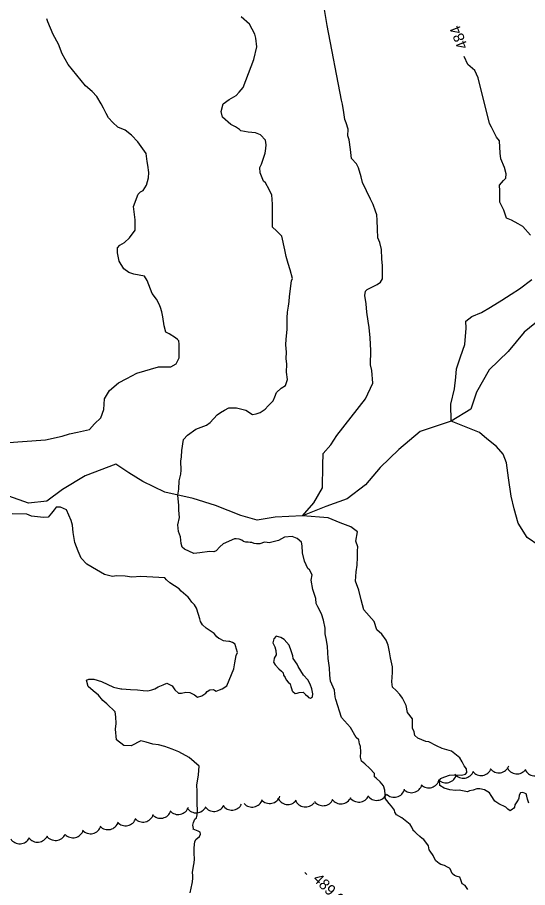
# Model space of a CAD drawing. Extents: x 642515 to 647219, y 6080136 to 6084356.
# Drawn here: x 644245.5 to 644387.6, y 6080895.6 to 6081138.3 of the extents above; entities that cross this region are included whole.
import ezdxf

# ---------------------------------------------------------------- set-up
doc = ezdxf.new("R2010")
doc.units = 0
for name, color, linetype in [('Level 1', 7, 'Continuous'), ('Level 2', 7, 'Continuous'), ('Level 3', 7, 'Continuous'), ('Level 4', 7, 'Continuous'), ('Level 44', 7, 'Continuous')]:
    doc.layers.add(name, color=color, linetype=linetype)

msp = doc.modelspace()

# ---------------------------------------------------------------- linework, layer by layer
at = {"layer": 'Level 1'}
for points in [[(644241.77, 6081019.67), (644253.35, 6081020.45), (644257.97, 6081021.56), (644260.03, 6081022.19), (644262.26, 6081022.66), (644265.61, 6081023.37), (644266.96, 6081024.91), (644268.78, 6081026.65), (644269.6, 6081028.97), (644269.73, 6081031.88), (644271.19, 6081034.24), (644273.64, 6081036.35), (644275.97, 6081037.63), (644278.79, 6081039.12), (644284.81, 6081040.81), (644288.2, 6081040.88), (644289.69, 6081041.7), (644290.54, 6081043.37), (644290.54, 6081047.17), (644290.47, 6081048.14), (644290.13, 6081048.44), (644289.53, 6081048.96), (644287.76, 6081050.06), (644286.84, 6081050.56), (644286.4, 6081052.31), (644285.99, 6081054.79), (644285.73, 6081056.23), (644285.41, 6081057.42), (644285.03, 6081058.36), (644284.21, 6081059.68), (644283.05, 6081061.3), (644281.68, 6081064.92), (644280.95, 6081066.17), (644277.93, 6081066.69), (644276.52, 6081067.17), (644275.16, 6081068.21), (644273.81, 6081070.3), (644273.41, 6081072.62), (644273.4, 6081073.99), (644274.08, 6081074.76), (644275.32, 6081075.49), (644276.77, 6081076.8), (644278.33, 6081078.92), (644278.3, 6081081.83), (644277.81, 6081085.6), (644279.12, 6081089), (644279.8, 6081089.61), (644280.5, 6081090.06), (644281.46, 6081091.5), (644282.05, 6081093.56), (644282.11, 6081095.02), (644281.81, 6081097.1), (644281.66, 6081098.14), (644281.35, 6081100.38), (644279.04, 6081103.62), (644277.3, 6081105.44), (644275.51, 6081106.86), (644273.51, 6081107.69), (644272.06, 6081108.97), (644270.92, 6081110.27), (644270.19, 6081111.51), (644269.53, 6081113), (644268.88, 6081114.17), (644267.62, 6081116.19), (644266.31, 6081117.64), (644264.51, 6081119.22), (644259.67, 6081125.12), (644257.94, 6081128.15), (644256.95, 6081130.83), (644255.48, 6081133.48), (644253.95, 6081137.1), (644253.73, 6081137.86)], [(644256.3, 6081001.69), (644255.7, 6081001), (644255.03, 6081000.07), (644254.05, 6080998.95), (644252.77, 6080998.87), (644249.43, 6080999.21), (644248.1, 6080999.77), (644244.06, 6080999.82)], [(644303.88, 6080951.86), (644305.83, 6080956.6), (644306.04, 6080958.31), (644306.43, 6080960.31), (644306.78, 6080961.22), (644306.52, 6080962.14), (644306.29, 6080963.09), (644306.14, 6080963.52), (644305.38, 6080963.96), (644304.72, 6080964.24), (644304.44, 6080964.26), (644303.58, 6080964.32), (644302.89, 6080964.48), (644301.88, 6080964.98), (644301.59, 6080965.08), (644301.04, 6080965.57), (644300.29, 6080966.45), (644299.48, 6080967.08), (644298.09, 6080968), (644297.1, 6080968.86), (644296.51, 6080969.83), (644296.34, 6080970.59), (644295.51, 6080973.28), (644295.42, 6080973.52), (644294.83, 6080974.49), (644294.7, 6080974.6), (644294.13, 6080975.25), (644293.47, 6080976.13), (644293.11, 6080976.59), (644291.14, 6080978.32), (644290.61, 6080978.93), (644289.31, 6080979.77), (644288, 6080980.62), (644287.01, 6080981.48), (644286.61, 6080981.98), (644279.88, 6080982.42), (644277.39, 6080982.17), (644275.51, 6080982.45), (644273.08, 6080982.61), (644271.96, 6080982.37), (644269.74, 6080982.95), (644267.55, 6080984.26), (644264.86, 6080985.86), (644263.3, 6080987.53), (644262.44, 6080989.49), (644261.47, 6080991.85), (644261.05, 6080994.65), (644260.83, 6080996.66), (644260.5, 6080998.01), (644259.17, 6081000.99), (644257.51, 6081001.69), (644256.3, 6081001.69)], [(644284.85, 6080935.4), (644283.22, 6080935.62), (644281.41, 6080936.14), (644279.93, 6080936.53), (644277.19, 6080935.13), (644275.17, 6080935.24), (644273.12, 6080936.88), (644272.84, 6080939.85), (644272.98, 6080941.4), (644272.94, 6080943.25), (644272.77, 6080944.61), (644270.43, 6080946.88), (644269.32, 6080947.78), (644268.09, 6080949.31), (644266.6, 6080950.46), (644265.22, 6080951.75), (644264.78, 6080953.49), (644265.41, 6080953.78), (644266.79, 6080953.79), (644268.89, 6080953.08), (644272.31, 6080951.53), (644274.36, 6080951.02), (644274.6, 6080951.04), (644277, 6080950.83), (644278.99, 6080950.76), (644280.57, 6080950.59), (644281.87, 6080950.51), (644282.91, 6080950.74), (644283.78, 6080951.04), (644284.71, 6080951.59), (644286.08, 6080952.21), (644287.14, 6080952.64), (644288.57, 6080951.85), (644289.37, 6080950.77), (644290.4, 6080949.87), (644291.25, 6080949.89), (644292.4, 6080950.16), (644293.54, 6080950), (644294.83, 6080949.4), (644295.72, 6080948.77), (644296.91, 6080949.09), (644297.96, 6080949.85), (644298.37, 6080950.32), (644299.07, 6080950.77), (644300.07, 6080950.88), (644300.44, 6080950.7), (644300.83, 6080950.36), (644301.77, 6080950.75), (644302.52, 6080951.08), (644303.88, 6080951.86)], [(644293.65, 6080894.14), (644294.16, 6080896.8), (644294.25, 6080897.25), (644294.34, 6080898.3), (644294.37, 6080899.03), (644294.32, 6080899.84), (644294.57, 6080901.59), (644294.75, 6080902.49), (644294.8, 6080903.58), (644294.73, 6080905.24), (644294.72, 6080905.92), (644294.79, 6080906.7), (644294.96, 6080908.52), (644295.32, 6080909.11), (644295.71, 6080909.38), (644296.2, 6080909.86), (644296.48, 6080910.52), (644296.4, 6080911.04), (644295.86, 6080911.37), (644294.49, 6080911.89), (644294.55, 6080912.13), (644294.34, 6080913.01), (644294.53, 6080913.75), (644294.91, 6080914.7), (644295.37, 6080915.06), (644295.55, 6080915.96), (644295.68, 6080917.06), (644295.68, 6080917.74), (644295.59, 6080918.42), (644295.56, 6080922.54), (644295.46, 6080924.15), (644295.91, 6080927.09), (644296.16, 6080929.45), (644293.32, 6080931.93), (644290.47, 6080933.51), (644288.65, 6080934.2), (644286.58, 6080934.95), (644284.85, 6080935.4)]]:
    msp.add_lwpolyline(points, dxfattribs=at)
msp.add_lwpolyline([(644325.25, 6080954.86), (644323.72, 6080957.26), (644323.43, 6080957.97), (644322.35, 6080959.51), (644322.23, 6080960.23), (644321.77, 6080961.62), (644321.18, 6080963.19), (644319.82, 6080964.84), (644318.85, 6080965.38), (644317.62, 6080965.78), (644316.9, 6080964.97), (644316.65, 6080963.9), (644317.21, 6080962.73), (644317.52, 6080961.7), (644317.6, 6080960.57), (644317.01, 6080959.64), (644316.9, 6080958.91), (644316.89, 6080958.46), (644317.34, 6080957.76), (644318.34, 6080956.66), (644319.07, 6080956.02), (644319.51, 6080955.49), (644319.67, 6080954.89), (644320.08, 6080954.23), (644320.4, 6080953.57), (644320.94, 6080952.87), (644321.45, 6080952.42), (644321.7, 6080951.75), (644321.82, 6080951.12), (644322.02, 6080950.48), (644322.24, 6080950.29), (644322.88, 6080949.73), (644323.48, 6080949.81), (644324.03, 6080950.01), (644325.08, 6080950.08), (644325.72, 6080949.52), (644326.28, 6080949.03), (644326.63, 6080948.65), (644327.13, 6080948.44), (644327.67, 6080948.8), (644327.77, 6080949.69), (644327.52, 6080951.05), (644327.03, 6080952.39), (644326.39, 6080953.56)], close=True, dxfattribs=at)
at = {"layer": 'Level 2'}
for points in [[(644344.5, 6081036.29), (644344.27, 6081039.84), (644343.84, 6081041.43), (644343.98, 6081045.41), (644343.75, 6081048.96), (644343.48, 6081051.78), (644343.2, 6081053.55), (644342.87, 6081056.12), (644342.63, 6081058.45), (644342.32, 6081060.7), (644342.48, 6081061.93), (644342.93, 6081062.45), (644344.27, 6081063.1), (644345.77, 6081063.77), (644346.69, 6081064.48), (644347.2, 6081065.41), (644347.2, 6081069.05), (644347.07, 6081070.99), (644346.9, 6081073.57), (644346.45, 6081075.49), (644345.95, 6081076.84), (644345.79, 6081079.26), (644345.71, 6081081.76), (644345.61, 6081083.22), (644345.3, 6081084.25), (644344.61, 6081086.07), (644343.86, 6081087.64), (644341.69, 6081092.28), (644341.26, 6081093.87), (644340.53, 6081096.34), (644339.97, 6081097.43), (644338.57, 6081098.96), (644338.32, 6081101.46), (644337.91, 6081104.11), (644337.58, 6081105.3), (644337.63, 6081107.09), (644337.1, 6081108.92), (644336.71, 6081109.86), (644336.42, 6081111.79), (644336.03, 6081114.12), (644335.79, 6081115.23), (644331.82, 6081136.05), (644331, 6081141.02)], [(644312.23, 6081130.07), (644311.91, 6081132.48), (644311.67, 6081133.6), (644310.19, 6081136.41), (644307.87, 6081138.44)], [(644320.52, 6081041.59), (644320.41, 6081043.2), (644320.45, 6081044.98), (644320.24, 6081046.99), (644320.38, 6081048.54), (644320.61, 6081051.23), (644320.63, 6081054.55), (644320.77, 6081056.09), (644320.99, 6081057.73), (644321.22, 6081059.04), (644321.29, 6081060.5), (644321.89, 6081064.83), (644322.17, 6081065.5), (644321.53, 6081067.88), (644320.93, 6081069.62), (644320.39, 6081071.61), (644320.03, 6081073.45), (644319.13, 6081077.27), (644317.73, 6081078.8), (644316.61, 6081079.78), (644316.6, 6081082.36), (644316.59, 6081086.17), (644316.34, 6081088.82), (644315.86, 6081089.84), (644315.67, 6081090.32), (644314.58, 6081092.19), (644314.06, 6081092.64), (644313.18, 6081094.93), (644313, 6081096.45), (644313.5, 6081097.38), (644314.52, 6081100.44), (644314.75, 6081101.75), (644314.76, 6081102.8), (644314.6, 6081104.01), (644313.21, 6081105.53), (644311.87, 6081106.09), (644309.76, 6081106.27), (644307.71, 6081106.7), (644307.36, 6081107), (644306.26, 6081107.82), (644305, 6081108.46), (644302.68, 6081110.49), (644302.25, 6081112.08), (644302.84, 6081114.15), (644304.54, 6081115.39), (644306.41, 6081116.49), (644307.24, 6081117.44), (644308.37, 6081118.73), (644311.41, 6081126.54), (644312.23, 6081130.07)], [(644388.46, 6081077.56), (644386.35, 6081080.01), (644385, 6081080.73), (644383.15, 6081081.75), (644381.81, 6081082.31), (644381.02, 6081084.53), (644379.9, 6081086.73), (644379.92, 6081087.62), (644379.93, 6081089.9), (644379.82, 6081091.51), (644380.96, 6081092.81), (644381.56, 6081093.5), (644381.65, 6081094.64), (644381.21, 6081096.4), (644380.15, 6081098.84), (644380.04, 6081100.46), (644379.82, 6081103.86), (644378.94, 6081104.93), (644378.1, 6081106.58), (644377.54, 6081107.68), (644377.06, 6081108.71), (644373.87, 6081121.41), (644372.92, 6081123.45), (644371.02, 6081125.11), (644369.95, 6081127.35)], [(644393.99, 6080988.79), (644387.53, 6080993.23), (644384.99, 6080997.29), (644383.91, 6081001.27), (644383.03, 6081004.79), (644382.36, 6081009.94), (644381.76, 6081014.12), (644380.79, 6081016.49), (644379.02, 6081018.65), (644376.29, 6081020.74), (644374.22, 6081022.55), (644366.39, 6081025.74), (644366.24, 6081030.44), (644367.26, 6081034.73), (644367.69, 6081038), (644367.87, 6081040.29), (644368.95, 6081043.61), (644370.18, 6081047.1), (644370.52, 6081051.67), (644370.48, 6081053.54), (644372.1, 6081054.86), (644374.78, 6081056.02), (644377.29, 6081057.48), (644380.49, 6081059.4), (644383.05, 6081061.12), (644385.39, 6081062.57), (644388.79, 6081065.23)], [(644306.42, 6080992.9), (644305.94, 6080992.86), (644305.94, 6080992.86), (644302.87, 6080991.45), (644301.88, 6080990.65), (644300.9, 6080989.53), (644300.19, 6080989.24), (644299.05, 6080989.33), (644296.32, 6080988.99), (644294.63, 6080988.79), (644292.04, 6080990), (644291.44, 6080990.52), (644291.13, 6080991.55), (644290.93, 6080993.4), (644290.42, 6080994.9), (644290.22, 6080996.75), (644290.65, 6080998.8), (644290.51, 6081000.9), (644290.43, 6081002.19), (644290.23, 6081005.09), (644290.45, 6081006.72), (644290.54, 6081009.08), (644291.06, 6081010.89), (644291.15, 6081012.03), (644291.07, 6081014.53), (644291.23, 6081015.76), (644291.27, 6081017.54), (644291.8, 6081020.57), (644292.85, 6081021.78), (644295.25, 6081023.47), (644297.46, 6081024.27), (644298.17, 6081024.56), (644299.17, 6081025.35), (644301.14, 6081027.43), (644302.06, 6081028.14), (644303.23, 6081028.78), (644304.41, 6081029.43), (644306.51, 6081029.4), (644309.14, 6081028.77), (644311, 6081027.6), (644312.04, 6081027.75), (644313.15, 6081028.15), (644314.55, 6081029.05), (644315.38, 6081030), (644316.74, 6081031.38), (644317.24, 6081032.47), (644317.72, 6081033.71), (644318.94, 6081034.93), (644320.18, 6081035.66), (644320.72, 6081037.31), (644320.51, 6081039.32), (644320.52, 6081041.59)], [(644368.76, 6080931.84), (644366.45, 6080933.64), (644363.8, 6080934.43), (644362.3, 6080935.14), (644360.11, 6080936.29), (644359.29, 6080936.4), (644357.05, 6080937.3), (644356.19, 6080938.06), (644356.04, 6080939.1), (644355.56, 6080940.12), (644355.55, 6080942.72), (644354.14, 6080944.41), (644353.77, 6080946.41), (644352.82, 6080948.45), (644352.03, 6080949.45), (644351.06, 6080950.6), (644350.03, 6080951.51), (644349.84, 6080953.04), (644349.99, 6080955.64), (644349.97, 6080957.18), (644349.48, 6080959.74), (644349.13, 6080961.42), (644348.76, 6080963.26), (644348.27, 6080964.6), (644347.02, 6080966.3), (644345.64, 6080967.51), (644344.92, 6080969.81), (644342.03, 6080973.1), (644341.28, 6080975.89), (644340.61, 6080978.6), (644339.72, 6080981.05), (644339.87, 6080983.66), (644340.15, 6080985.54), (644340.25, 6080987.74), (644340.29, 6080989.52), (644340.38, 6080990.66), (644339.79, 6080992.25), (644340.26, 6080994.87), (644338.39, 6080996.21), (644335.4, 6080997.3), (644332.06, 6080998.7), (644324.9, 6080999.31), (644328.07, 6081002.92), (644330.54, 6081007.14), (644330.61, 6081013.47), (644330.72, 6081016.72), (644332.83, 6081019.13), (644334.45, 6081021.67), (644342.52, 6081031.94), (644344.5, 6081036.29)], [(644340.84, 6080935.75), (644340.61, 6080936.87), (644339.92, 6080937.47), (644338.28, 6080940.27), (644335.83, 6080943.02), (644334.2, 6080948.09), (644334.07, 6080948.81), (644333.86, 6080950.66), (644332.73, 6080953.18), (644332.53, 6080954.86), (644332.48, 6080956.88), (644332.06, 6080959.52), (644331.93, 6080962.83), (644331.65, 6080964.6), (644331.28, 6080966.43), (644331.26, 6080967.97), (644330.79, 6080970.2), (644330.19, 6080971.94), (644329.17, 6080973.9), (644328.78, 6080974.84), (644328.61, 6080976.21), (644328.29, 6080977.4), (644327.8, 6080978.74), (644327.38, 6080981.39), (644327.6, 6080982.86), (644326.86, 6080984.27), (644326.43, 6080984.64), (644325.96, 6080985.66), (644325.49, 6080986.68), (644324.93, 6080988.99), (644324.8, 6080990.93), (644324.65, 6080991.97), (644323.45, 6080993.02), (644322.04, 6080993.49), (644319.95, 6080993.35), (644318.23, 6080992.43), (644315.68, 6080991.78), (644315.11, 6080991.82), (644314.3, 6080991.93), (644313.03, 6080991.52), (644312.14, 6080991.46), (644311.44, 6080991.61), (644310.82, 6080991.86), (644310.33, 6080991.9), (644309.8, 6080991.99), (644309.16, 6080991.95), (644308.49, 6080992.15), (644307.98, 6080992.52), (644307.32, 6080992.8), (644306.42, 6080992.9)], [(644369.41, 6080896.71), (644369.05, 6080897.78), (644368.72, 6080898.52), (644367.98, 6080898.72), (644367.31, 6080899), (644366.59, 6080899.56), (644366.34, 6080900.23), (644366.1, 6080900.9), (644365.88, 6080901.09), (644365.34, 6080901.33), (644364.46, 6080901.8), (644363.43, 6080902.1), (644363.01, 6080902.31), (644362.11, 6080903.1), (644361.64, 6080903.96), (644361.36, 6080904.59), (644360.51, 6080905.79), (644360.24, 6080906.17), (644360.05, 6080907.25), (644358.76, 6080909.07), (644358.25, 6080909.36), (644357.65, 6080909.88), (644356.66, 6080910.75), (644356.19, 6080911.16), (644355.76, 6080911.54), (644355.79, 6080911.66), (644355.42, 6080912.45), (644354.92, 6080913.18), (644352.57, 6080915.09), (644351.1, 6080915.92), (644350.65, 6080916.62), (644350.52, 6080917.26), (644349.76, 6080918.38), (644349.07, 6080919.06), (644348.45, 6080919.91), (644348.05, 6080920.41), (644347.96, 6080921.09), (644347.95, 6080921.94), (644347.84, 6080922.42), (644347.85, 6080922.78), (644347.53, 6080923.98), (644346.56, 6080925.13), (644345.45, 6080926.1), (644345.02, 6080926.48), (644344.95, 6080927.45), (644343.73, 6080928.82), (644342.27, 6080930.1), (644341.41, 6080930.85), (644341.09, 6080932.04), (644341.15, 6080933.51), (644341.06, 6080934.96), (644340.84, 6080935.75)], [(644387.96, 6080919.14), (644387.6, 6080920.29), (644387.42, 6080921.13), (644387.22, 6080921.77), (644386.3, 6080922.19), (644385.7, 6080922.03), (644385.34, 6080921.44), (644385.19, 6080920.58), (644385.13, 6080920.33), (644384.65, 6080919.53), (644384.06, 6080918.68), (644383.98, 6080918.07), (644383.68, 6080917.64), (644383.41, 6080917.5), (644382.79, 6080917.06), (644382.11, 6080917.5), (644381.59, 6080918.03), (644379.66, 6080918.95), (644378.56, 6080919.77), (644377.48, 6080921.32), (644377.03, 6080922.02), (644375.67, 6080922.9), (644374.36, 6080923.14), (644373.47, 6080923.16), (644372.52, 6080922.77), (644371.48, 6080922.62), (644370.93, 6080922.34), (644368.62, 6080922.84), (644367.58, 6080922.69), (644365.94, 6080922.9), (644364.37, 6080923.36), (644363.19, 6080924.1), (644363.1, 6080925.39), (644363.38, 6080926.05), (644364.57, 6080926.54), (644365.84, 6080926.95), (644367.61, 6080927.07), (644369.24, 6080927.01), (644370.36, 6080927.25), (644370.74, 6080927.68), (644370.59, 6080928.72), (644369.96, 6080929.57), (644369.4, 6080930.67), (644368.76, 6080931.84)], [(644371.01, 6080895.08), (644370.25, 6080896.2), (644369.41, 6080896.71)]]:
    msp.add_lwpolyline(points, dxfattribs=at)
at = {"layer": 'Level 3'}
msp.add_line((644325.59, 6080899.84), (644326.16, 6080899.28), dxfattribs=at)
at = {"layer": 'Level 4'}
msp.add_lwpolyline([(644392.62, 6081055.39), (644386.68, 6081050.51), (644382.25, 6081045.09), (644376.9, 6081040.02), (644373.41, 6081033.77), (644371.86, 6081029.03), (644366.39, 6081025.74), (644357.74, 6081022.79), (644351.73, 6081017.84), (644346.55, 6081012.78), (644342.49, 6081007.96), (644337.4, 6081004.05), (644331.46, 6081001.94), (644324.9, 6080999.31), (644317.3, 6080998.95), (644312.33, 6080998.13), (644307.79, 6080999.36), (644300.71, 6081002.2), (644294.51, 6081004.12), (644286.53, 6081005.93), (644280.43, 6081008.83), (644276.54, 6081011.32), (644272.89, 6081013.74), (644264.38, 6081010.41), (644258.08, 6081006.67), (644253.69, 6081003.38), (644248.55, 6081002.87), (644243.09, 6081004.76)], dxfattribs=at)
at = {"layer": 'Level 44'}
for centre, start, end in [((644379.65, 6080930.64), 218.5812, 338.5591), ((644384.69, 6080930.36), 203.8524, 323.8303), ((644364.9, 6080927.84), 226.1494, 346.1274), ((644369.76, 6080929.15), 218.5812, 338.5591), ((644374.71, 6080929.89), 218.5812, 338.5591), ((644389.66, 6080929.82), 203.8524, 323.8303), ((644355.29, 6080925.1), 224.7836, 344.7615), ((644360.1, 6080926.45), 226.1494, 346.1274), ((644345.6, 6080922.95), 215.537, 335.5149), ((644350.46, 6080923.83), 224.7836, 344.7615), ((644310.88, 6080921.07), 221.7005, 341.6784), ((644315.78, 6080922.08), 221.7005, 341.6784), ((644320.82, 6080921.81), 202.1373, 322.1152), ((644325.77, 6080921.12), 202.1373, 322.1152), ((644330.67, 6080921.46), 215.9835, 335.9614), ((644335.64, 6080921.98), 215.9835, 335.9614), ((644340.62, 6080922.47), 215.537, 335.5149), ((644285.39, 6080917.96), 222.184, 342.162), ((644290.28, 6080919.01), 222.184, 342.162), ((644295.29, 6080919.47), 214.3603, 334.3383), ((644300.28, 6080919.85), 214.3603, 334.3383), ((644305.26, 6080920.23), 214.3603, 334.3383), ((644275.62, 6080915.85), 222.184, 342.162), ((644280.5, 6080916.9), 222.184, 342.162), ((644265.85, 6080913.65), 223.1226, 343.1005), ((644270.72, 6080914.79), 223.1226, 343.1005), ((644246.15, 6080910.84), 213.2469, 333.2249), ((644251.11, 6080911.28), 215.7661, 335.744), ((644256.09, 6080911.78), 215.7661, 335.744), ((644260.98, 6080912.52), 223.1226, 343.1005)]:
    msp.add_arc(centre, 3, start, end, dxfattribs=at)

# ---------------------------------------------------------------- texts
at = {"layer": 'Level 2'}
msp.add_text('484', height=3, rotation=111.6772, dxfattribs=at).set_placement((644371.1, 6081130.09))
at = {"layer": 'Level 3'}
msp.add_text('489,6', height=3, rotation=315.59, dxfattribs=at).set_placement((644327.62, 6080897.8))

doc.saveas('drawing.dxf')
